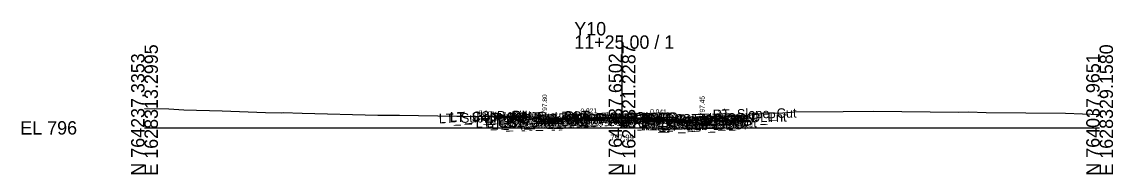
# Model space of a CAD drawing. Extents: x -26 to 203, y -10 to 4017.
# Drawn here: x -25.7 to 202.8, y 2490.3 to 2522.2 of the extents above; entities that cross this region are included whole.
import ezdxf

# ---------------------------------------------------------------- set-up
doc = ezdxf.new("R2010")
doc.units = 0
for name, color, linetype in [('Default', 7, 'Continuous'), ('Exist CMT Pavement', 7, 'Continuous'), ('Exist Cross Section Cell', 7, 'Continuous'), ('Exist XS Center Line Elevation Label', 7, 'Continuous'), ('Exist XS Ground Line', 7, 'Continuous'), ('Prop CMT Conc Surface', 7, 'Continuous'), ('Prop CMT Concrete Structures', 7, 'Continuous'), ('Prop CMT Pvmt Course 1', 7, 'Continuous'), ('Prop CMT Pvmt Course 1 CG', 7, 'Continuous'), ('Prop CMT Pvmt Course 1 Wedge', 7, 'Continuous'), ('Prop CMT Pvmt Course 2', 7, 'Continuous'), ('Prop CMT Pvmt Course 2 Wedge', 7, 'Continuous'), ('Prop CMT Pvmt Course 3', 7, 'Continuous'), ('Prop CMT Pvmt Surface', 7, 'Continuous'), ('Prop CMT Pvmt Wedge Surface 1', 7, 'Continuous'), ('Prop CMT Pvmt Wedge Surface 2', 7, 'Continuous'), ('Prop CMT Pvmt Wedge Surface 3', 7, 'Continuous'), ('Prop CMT Slope Grass', 7, 'Continuous'), ('Prop CMT Subgrade Earthwork', 7, 'Continuous'), ('Prop XS Hydro Elevations', 7, 'Continuous'), ('Prop XS SE Text', 7, 'Continuous'), ('Prop XS Side Slope Text', 7, 'Continuous'), ('Scratch_Level_0', 7, 'Continuous')]:
    doc.layers.add(name, color=color, linetype=linetype)

msp = doc.modelspace()

# ---------------------------------------------------------------- linework, layer by layer
at = {"layer": 'Exist CMT Pavement'}
for points in [[(100, 2501.99), (92.55, 2501.95), (87.36, 2502.03)], [(100, 2501.99), (100.88, 2502), (111.46, 2501.41), (114.78, 2501.24)]]:
    msp.add_lwpolyline(points, dxfattribs=at)
at = {"layer": 'Exist Cross Section Cell'}
for p, q in [((100, 2500), (100, 2519.36)), ((0, 2500), (100, 2500)), ((100, 2500), (200, 2500))]:
    msp.add_line(p, q, dxfattribs=at)
at = {"layer": 'Exist XS Ground Line'}
msp.add_lwpolyline([(0, 2504.06), (5.08, 2503.97), (8.23, 2503.81), (16.24, 2503.59), (25.31, 2503.19), (28.71, 2503.18), (29.01, 2503.19), (33.01, 2503.08), (48.85, 2502.66), (53.37, 2502.63), (65.37, 2502.44), (66.82, 2502.45), (73.26, 2502.35), (74.38, 2502.37), (76.3, 2502.36), (79.35, 2502.35), (81.05, 2502.32), (84.69, 2502.39), (84.75, 2502.07), (92.55, 2501.95), (100, 2501.99), (100.88, 2502), (111.46, 2501.41), (115.17, 2501.22), (116.48, 2501.73), (118.38, 2502.05), (124.66, 2502.48), (128.73, 2502.91), (130.14, 2503.22), (132.85, 2503.07), (136.09, 2503.36), (146.3, 2503.42), (152.6, 2503.5), (170.55, 2503.3), (172.54, 2503.33), (176.26, 2503.25), (192.87, 2503.05), (200, 2502.78)], dxfattribs=at)
at = {"layer": 'Prop CMT Conc Surface'}
for points in [[(85.8, 2501.92), (83.8, 2501.8)], [(114.78, 2501.62), (116.78, 2501.45)], [(116.78, 2501.45), (116.78, 2501.95), (117.28, 2501.95)]]:
    msp.add_lwpolyline(points, dxfattribs=at)
at = {"layer": 'Prop CMT Concrete Structures'}
for p, q in [((73.8, 2502.18), (71.23, 2502.38)), ((79.3, 2502.07), (73.8, 2502.18)), ((83.3, 2501.91), (79.3, 2502.07)), ((83.8, 2501.8), (83.3, 2501.91))]:
    msp.add_line(p, q, dxfattribs=at)
for points in [[(83.3, 2501.91), (83.3, 2501.29), (85.8, 2501.34)], [(85.8, 2501.92), (83.8, 2501.8)], [(85.8, 2501.34), (85.8, 2501.92)], [(114.78, 2501.62), (116.78, 2501.45), (116.78, 2501.95), (117.28, 2501.95)], [(117.28, 2501.95), (117.28, 2500.93), (114.78, 2501.03)], [(114.78, 2501.03), (114.78, 2501.62)]]:
    msp.add_lwpolyline(points, dxfattribs=at)
at = {"layer": 'Prop CMT Pvmt Course 1'}
for points in [[(100, 2502.22), (85.8, 2501.92)], [(85.8, 2501.92), (85.8, 2501.67)], [(85.8, 2501.67), (87.36, 2501.71)], [(87.36, 2501.83), (100, 2502.09)], [(87.36, 2501.71), (87.36, 2501.83)], [(100, 2501.97), (100, 2502.22)], [(100, 2502.22), (114.78, 2501.62)], [(100, 2501.97), (100, 2502.22)], [(100, 2502.09), (100, 2501.97), (100, 2501.97)], [(114.78, 2501.49), (100, 2502.09)], [(100, 2502.09), (100, 2501.97), (100, 2501.97)], [(114.78, 2501.62), (114.78, 2501.37), (114.78, 2501.37), (114.78, 2501.49)]]:
    msp.add_lwpolyline(points, dxfattribs=at)
at = {"layer": 'Prop CMT Pvmt Course 1 CG'}
for points in [[(85.8, 2501.34), (82.8, 2501.28), (82.46, 2500.94)], [(82.46, 2500.94), (85.8, 2501.01)], [(85.8, 2501.01), (85.8, 2501.34)], [(114.78, 2501.03), (117.78, 2500.91), (118.12, 2500.56)], [(114.78, 2500.7), (114.78, 2501.03)], [(118.12, 2500.56), (114.78, 2500.7)]]:
    msp.add_lwpolyline(points, dxfattribs=at)
at = {"layer": 'Prop CMT Pvmt Course 1 Wedge'}
for points in [[(93.43, 2501.96), (100, 2502.09)], [(100, 2501.99), (93.43, 2501.96)], [(100, 2502.09), (100, 2501.99)], [(100, 2502.09), (100.88, 2502.06), (111.46, 2501.63), (114.78, 2501.49)], [(100, 2501.99), (100, 2502.09)], [(114.78, 2501.37), (111.46, 2501.5), (105.49, 2501.74), (100.88, 2502), (100, 2501.99)], [(114.78, 2501.49), (114.78, 2501.37)]]:
    msp.add_lwpolyline(points, dxfattribs=at)
at = {"layer": 'Prop CMT Pvmt Course 2'}
for points in [[(87.36, 2501.71), (85.8, 2501.67)], [(85.8, 2501.67), (85.8, 2501.34)], [(85.8, 2501.34), (87.36, 2501.37)], [(87.36, 2501.37), (87.36, 2501.71)], [(114.78, 2501.03), (114.78, 2501.03), (114.78, 2501.37), (114.78, 2501.37)], [(114.78, 2501.37), (114.78, 2501.03)]]:
    msp.add_lwpolyline(points, dxfattribs=at)
at = {"layer": 'Prop CMT Pvmt Course 2 Wedge'}
for points in [[(114.78, 2501.24), (111.46, 2501.41), (105.49, 2501.74)], [(105.49, 2501.74), (111.46, 2501.5)], [(111.46, 2501.5), (114.78, 2501.37)], [(114.78, 2501.37), (114.78, 2501.24)]]:
    msp.add_lwpolyline(points, dxfattribs=at)
at = {"layer": 'Prop CMT Pvmt Course 3'}
for points in [[(87.36, 2501.37), (85.8, 2501.34)], [(85.8, 2501.34), (85.8, 2501.01)], [(85.8, 2501.01), (87.36, 2501.04)], [(87.36, 2501.04), (87.36, 2501.37)], [(114.78, 2501.03), (114.78, 2501.03), (114.78, 2500.7), (114.78, 2500.7)], [(114.78, 2500.7), (114.78, 2501.03)]]:
    msp.add_lwpolyline(points, dxfattribs=at)
at = {"layer": 'Prop CMT Pvmt Surface'}
for points in [[(100, 2502.22), (85.8, 2501.92)], [(100, 2502.22), (114.78, 2501.62)]]:
    msp.add_lwpolyline(points, dxfattribs=at)
at = {"layer": 'Prop CMT Pvmt Wedge Surface 1'}
for points in [[(85.8, 2501.67), (85.8, 2501.92)], [(87.36, 2501.71), (85.8, 2501.67)], [(100, 2502.09), (87.36, 2501.83)], [(87.36, 2501.83), (87.36, 2501.71)], [(100, 2502.09), (114.78, 2501.49)], [(114.78, 2501.37), (114.78, 2501.62)], [(114.78, 2501.49), (114.78, 2501.37), (114.78, 2501.37)]]:
    msp.add_lwpolyline(points, dxfattribs=at)
at = {"layer": 'Prop CMT Pvmt Wedge Surface 2'}
for points in [[(100, 2501.97), (85.8, 2501.67)], [(85.8, 2501.67), (85.8, 2501.92)], [(100, 2501.97), (114.78, 2501.37)], [(114.78, 2501.37), (114.78, 2501.62)]]:
    msp.add_lwpolyline(points, dxfattribs=at)
at = {"layer": 'Prop CMT Pvmt Wedge Surface 3'}
for points in [[(85.8, 2501.34), (85.8, 2501.92)], [(100, 2501.63), (85.8, 2501.34)], [(100, 2501.63), (114.78, 2501.03)], [(114.78, 2501.03), (114.78, 2501.62)]]:
    msp.add_lwpolyline(points, dxfattribs=at)
at = {"layer": 'Prop CMT Slope Grass'}
for points in [[(117.28, 2501.95), (120.78, 2502.02)], [(120.78, 2502.02), (121.5, 2502.26)]]:
    msp.add_lwpolyline(points, dxfattribs=at)
at = {"layer": 'Prop CMT Subgrade Earthwork'}
for points in [[(85.8, 2501.01), (82.46, 2500.94), (81.41, 2501.99)], [(87.36, 2501.04), (85.8, 2501.01)], [(87.36, 2501.04), (87.37, 2502.03)], [(114.78, 2500.7), (114.76, 2501.25)], [(114.78, 2500.7), (118.12, 2500.56), (119.56, 2502)], [(114.78, 2500.7), (114.78, 2500.7)]]:
    msp.add_lwpolyline(points, dxfattribs=at)

# ---------------------------------------------------------------- texts
at = {"layer": 'Default'}
msp.add_text('-', height=0.0001, dxfattribs=at).set_placement((0, 2500))
at = {"layer": 'Exist Cross Section Cell'}
for s, p in [('Y10', (90, 2519.36)), ('11+25.00 / 1', (90, 2516.56)), ('EL 796', (-26, 2498.6))]:
    msp.add_text(s, height=2.8, dxfattribs=at).set_placement(p)
for s, p in [('E 1628313.2995', (2.8, 2490)), ('E 1628321.2287', (102.8, 2490)), ('E 1628329.1580', (202.8, 2490)), ('N 764237.3353', (0, 2490)), ('N 764137.6502', (100, 2490)), ('N 764037.9651', (200, 2490))]:
    msp.add_text(s, height=2.8, rotation=90, dxfattribs=at).set_placement(p)
at = {"layer": 'Exist XS Center Line Elevation Label'}
msp.add_text('797.99', height=1.2, dxfattribs=at).set_placement((97.56, 2497.39))
at = {"layer": 'Prop XS Hydro Elevations'}
for s, p in [('797.80', (84.3, 2502.8)), ('797.45', (117.28, 2502.45))]:
    msp.add_text(s, height=1, rotation=90, dxfattribs=at).set_placement(p)
at = {"layer": 'Prop XS SE Text'}
for s, rotation, p in [('8.00%', 355.5558, (69.95, 2502.72)), ('2.00%', 358.8542, (74.95, 2502.35)), ('4.00%', 357.7094, (79.17, 2502.39)), ('0.021', 1.1887, (91.31, 2503.04)), ('0.041', 357.6657, (105.86, 2502.98))]:
    msp.add_text(s, height=1, rotation=rotation, dxfattribs=at).set_placement(p)
at = {"layer": 'Prop XS Side Slope Text'}
msp.add_text('3:1', height=1, rotation=18.4332, dxfattribs=at).set_placement((120.26, 2502.62))
at = {"layer": 'Scratch_Level_0'}
for s, p in [('LT_Sub_Trench_Out_DLT', (61.64, 2500.96)), ('LT_Slope_Fill', (63.9, 2501.17)), ('LT_CSLP_Pnt', (64, 2501.3)), ('LT_CG1_Shelf_Out', (69.37, 2500.01)), ('LT_CG_Top_Face', (71.08, 2501.05)), ('LT_CG_Top_BOC', (71.61, 2501.07)), ('LT_CG_Bot_BOC', (71.64, 2500.05)), ('LT_CG_Top_Gut', (72.06, 2500.57)), ('LT_PV_Sub_Tie_Out', (72.34, 2500.73)), ('LT_PV_OEEOP_EG', (74.92, 2500.78)), ('LT_CG_Bot_IE', (75.74, 2500.14)), ('LT_PV2_OEOT', (76, 2500.48)), ('LT_PV3_OEOT', (76, 2500.14)), ('LT_PV1_OEOT', (76.56, 2500.74)), ('LT_PV2_OEEOP', (76.69, 2500.49)), ('LT_PV3_OEEOP', (76.69, 2500.16)), ('LT_PV1_OEEOP', (77.25, 2500.63)), ('RT_PV_IEEOP_EG', (88.16, 2500.76)), ('LT_PV_IEEOP_EG', (88.21, 2500.76)), ('RT_PV2_IEEOP', (89.93, 2500.77)), ('RT_PV3_IEEOP', (89.93, 2500.43)), ('LT_PV2_IEEOP', (89.97, 2500.77)), ('LT_PV3_IEEOP', (89.97, 2500.43)), ('RT_PV1_IEEOP', (90.49, 2500.9)), ('LT_PV1_IEEOP', (90.54, 2500.9)), ('PV2_PGL', (93.93, 2500.85)), ('PV1_PGL', (94.49, 2501.11)), ('RT_Sub_Trench_Out_DLT', (100.11, 2500.61)), ('RT_PV_OEEOP_EG', (102.3, 2499.99)), ('RT_CG_Top_Face', (104.01, 2500.7)), ('RT_PV2_OEEOP', (104.06, 2500.15)), ('RT_PV1_OEEOP', (104.63, 2500.29)), ('RT_PV2_OEOT', (104.93, 2500.17)), ('RT_CG_Top_Gut', (104.99, 2500.22)), ('RT_PV1_OEOT', (105.49, 2500.43)), ('RT_CG_Top_BOC', (105.54, 2500.72)), ('RT_CSLP_Pnt', (116.93, 2500.95)), ('RT_Slope_Cut', (119.01, 2501.81)), ('LT_Sub_OEOP', (72.59, 2499.74)), ('LT_Sub_OEOT', (75.9, 2499.81)), ('LT_Sub_OEEOP', (76.59, 2499.82)), ('RT_PV_Sub_Tie_Out', (99.68, 2499.94)), ('RT_Sub_OEEOP', (103.96, 2499.48)), ('RT_PV3_OEEOP', (104.06, 2499.82)), ('RT_CG1_Shelf_Out', (104.3, 2499.64)), ('RT_CG_Bot_IE', (104.67, 2499.83)), ('RT_Sub_OEOT', (104.83, 2499.5)), ('RT_PV3_OEOT', (104.93, 2499.83)), ('RT_CG_Bot_BOC', (105.57, 2499.7)), ('RT_Sub_OEOP', (108.21, 2499.36))]:
    msp.add_text(s, height=2, rotation=1.1458, dxfattribs=at).set_placement(p)

doc.saveas('drawing.dxf')
